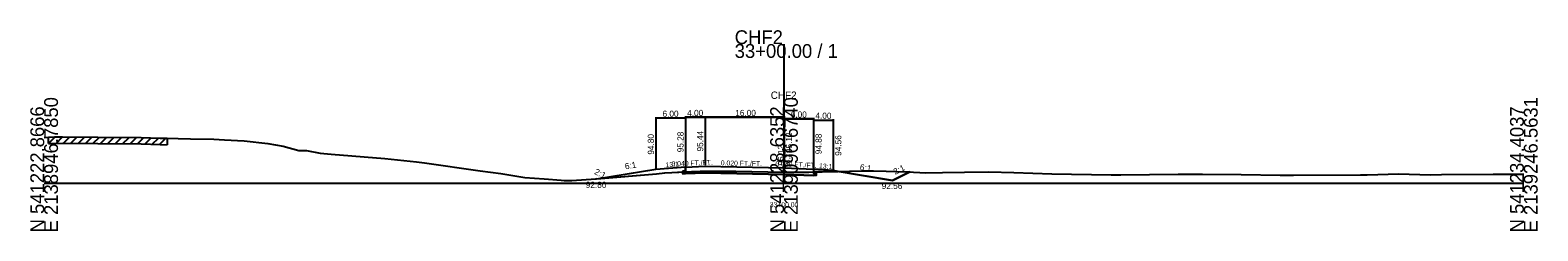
# Model space of a CAD drawing. Extents: x -12831 to 2303, y -10 to 39065.
# Drawn here: x 997.2 to 1302.8, y 5990.3 to 6031.1 of the extents above; entities that cross this region are included whole.
import ezdxf

# ---------------------------------------------------------------- set-up
doc = ezdxf.new("R2010")
doc.units = 0
for name, color, linetype in [('Level 5', 7, 'Continuous'), ('Level 53', 7, 'Continuous'), ('Level 54', 7, 'Continuous'), ('Level 55', 7, 'Continuous'), ('Level 7', 7, 'Continuous'), ('RD_GPK_XS_Cell', 7, 'Continuous'), ('RD_XS_EwShp', 7, 'Continuous'), ('RD_XS_ExGround', 7, 'Continuous'), ('RD_XS_ExPaveRet', 7, 'Continuous'), ('RD_XS_Pave', 7, 'Continuous'), ('RD_XS_TX_Baseline', 7, 'Continuous'), ('RD_XS_TX_Ditch', 7, 'Continuous'), ('RD_XS_TX_Elev_EX', 7, 'Continuous'), ('RD_XS_TX_Elev_PR', 7, 'Continuous'), ('RD_XS_TX_Station', 7, 'Continuous')]:
    doc.layers.add(name, color=color, linetype=linetype)

msp = doc.modelspace()

# ---------------------------------------------------------------- linework, layer by layer
at = {"layer": 'Level 5'}
for p, q in [((1130, 6002.45), (1129.5, 6002.43)), ((1129.5, 6002.43), (1129.5, 6001.93)), ((1129.5, 6001.93), (1130, 6001.95)), ((1130, 6003.28), (1130, 6002.45)), ((1134, 6002.11), (1130, 6001.95)), ((1134, 6002.11), (1130, 6001.95)), ((1130, 6001.95), (1134, 6002.11)), ((1150, 6001.79), (1134, 6002.11)), ((1150, 6001.79), (1134, 6002.11)), ((1134, 6002.11), (1150, 6001.79)), ((1134, 6002.11), (1150, 6001.79)), ((1156, 6001.55), (1150, 6001.79)), ((1150, 6001.79), (1156, 6001.55)), ((1150, 6001.79), (1156, 6001.55)), ((1156, 6002.88), (1156, 6002.05)), ((1156, 6002.05), (1156.5, 6002.03)), ((1156.5, 6001.53), (1156, 6001.55)), ((1156.5, 6002.03), (1156.5, 6001.53))]:
    msp.add_line(p, q, dxfattribs=at)
at = {"layer": 'Level 54'}
for p, q in [((1124, 6013.43), (1124, 6003)), ((1130, 6013.23), (1124, 6013.23)), ((1130, 6013.59), (1130, 6003.48)), ((1130, 6013.59), (1130, 6003.48)), ((1130, 6013.59), (1130, 6003.48)), ((1130, 6013.43), (1130, 6003.48)), ((1130, 6013.39), (1134, 6013.39)), ((1130, 6013.39), (1134, 6013.39)), ((1134, 6013.39), (1130, 6013.39)), ((1134, 6013.59), (1134, 6003.64)), ((1134, 6013.59), (1134, 6003.64)), ((1134, 6013.59), (1134, 6003.64)), ((1134, 6013.59), (1134, 6003.64)), ((1134, 6013.59), (1134, 6003.64)), ((1134, 6013.59), (1134, 6003.64)), ((1134, 6013.59), (1134, 6003.64)), ((1134, 6013.39), (1150, 6013.39)), ((1134, 6013.39), (1150, 6013.39)), ((1150, 6013.39), (1134, 6013.39)), ((1150, 6013.39), (1134, 6013.39)), ((1150, 6013.59), (1150, 6003.32)), ((1150, 6013.59), (1150, 6003.32)), ((1150, 6013.59), (1150, 6003.32)), ((1150, 6013.59), (1150, 6003.32)), ((1150, 6013.27), (1150, 6003.32)), ((1150, 6013.27), (1150, 6003.32)), ((1150, 6013.27), (1150, 6003.32)), ((1150, 6013.07), (1156, 6013.07)), ((1156, 6013.07), (1150, 6013.07)), ((1156, 6013.07), (1150, 6013.07)), ((1156, 6013.27), (1156, 6003.08)), ((1156, 6013.27), (1156, 6003.08)), ((1156, 6013.27), (1156, 6003.08)), ((1156, 6013.03), (1156, 6003.08)), ((1156, 6012.83), (1160, 6012.83)), ((1160, 6013.03), (1160, 6002.76))]:
    msp.add_line(p, q, dxfattribs=at)
at = {"layer": 'Level 7'}
for p, q in [((1112, 6000.8), (1111.88, 6000.86)), ((1124, 6002.8), (1112, 6000.8)), ((1130, 6003.28), (1124, 6002.8)), ((1156, 6002.88), (1160, 6002.56)), ((1160, 6002.56), (1172, 6000.56)), ((1172, 6000.56), (1175.48, 6002.3))]:
    msp.add_line(p, q, dxfattribs=at)
at = {"layer": 'RD_GPK_XS_Cell'}
for p, q in [((1150, 6000), (1150, 6028.25)), ((1000, 6000), (1150, 6000)), ((1150, 6000), (1300, 6000))]:
    msp.add_line(p, q, dxfattribs=at)
at = {"layer": 'RD_XS_EwShp'}
for points in [[(1112.84, 6000.94), (1112, 6000.8), (1111.88, 6000.86)], [(1112.84, 6000.94), (1124.13, 6001.88), (1125.81, 6002.1), (1127.26, 6002.18), (1129.5, 6002.29), (1129.5, 6002.43), (1130, 6002.45), (1130, 6003.28), (1124, 6002.8)], [(1129.5, 6002.29), (1132.97, 6002.46), (1140.22, 6002.46), (1146.75, 6002.3), (1150, 6002.27), (1153.19, 6002.25), (1155.01, 6002.26), (1156, 6002.28), (1156, 6002.05), (1156.5, 6002.03), (1156.5, 6001.53), (1156, 6001.55), (1150, 6001.79), (1134, 6002.11), (1130, 6001.95), (1129.5, 6001.93)], [(1156, 6002.28), (1160.97, 6002.4), (1160, 6002.56), (1156, 6002.88)], [(1168.13, 6002.54), (1170.73, 6002.44), (1175.07, 6002.33), (1175.48, 6002.3), (1172, 6000.56), (1160.97, 6002.4), (1165.98, 6002.51)]]:
    msp.add_lwpolyline(points, close=True, dxfattribs=at)
at = {"layer": 'RD_XS_ExGround'}
for p, q in [((1000, 6009.29), (1000.9, 6009.36)), ((1000.9, 6009.36), (1002.11, 6009.39)), ((1002.11, 6009.39), (1003.7, 6009.42)), ((1003.7, 6009.42), (1010.87, 6009.35)), ((1010.87, 6009.35), (1019.69, 6009.27)), ((1019.69, 6009.27), (1023.5, 6009.15)), ((1023.5, 6009.15), (1024.93, 6009.12)), ((1024.93, 6009.12), (1027.17, 6009.1)), ((1027.17, 6009.1), (1029.65, 6009.02)), ((1029.65, 6009.02), (1034.39, 6008.94)), ((1034.39, 6008.94), (1036.56, 6008.8)), ((1036.56, 6008.8), (1040.57, 6008.57)), ((1040.57, 6008.57), (1045.34, 6008.04)), ((1045.34, 6008.04), (1048.48, 6007.53)), ((1048.48, 6007.53), (1051.63, 6006.64)), ((1051.63, 6006.64), (1053.17, 6006.61)), ((1053.17, 6006.61), (1055.96, 6006.12)), ((1055.96, 6006.12), (1058.22, 6005.91)), ((1058.22, 6005.91), (1069.1, 6005.04)), ((1069.1, 6005.04), (1075.49, 6004.36)), ((1075.49, 6004.36), (1077.11, 6004.16)), ((1077.11, 6004.16), (1088.43, 6002.54)), ((1088.43, 6002.54), (1092.56, 6001.94)), ((1092.56, 6001.94), (1097.43, 6001.13)), ((1097.43, 6001.13), (1101.38, 6000.85)), ((1101.38, 6000.85), (1104.84, 6000.61)), ((1104.84, 6000.61), (1105.44, 6000.56)), ((1105.44, 6000.56), (1106.99, 6000.52)), ((1106.99, 6000.52), (1111.87, 6000.86)), ((1111.87, 6000.86), (1124.13, 6001.88)), ((1124.13, 6001.88), (1125.81, 6002.1)), ((1125.81, 6002.1), (1127.26, 6002.18)), ((1127.26, 6002.18), (1132.97, 6002.46)), ((1132.97, 6002.46), (1140.22, 6002.46)), ((1140.22, 6002.46), (1146.75, 6002.3)), ((1146.75, 6002.3), (1150, 6002.27)), ((1150, 6002.27), (1153.19, 6002.25)), ((1153.19, 6002.25), (1155.01, 6002.26)), ((1155.01, 6002.26), (1165.98, 6002.51)), ((1165.98, 6002.51), (1168.13, 6002.54)), ((1168.13, 6002.54), (1170.73, 6002.44)), ((1170.73, 6002.44), (1175.07, 6002.33)), ((1175.07, 6002.33), (1178.76, 6002.08)), ((1178.76, 6002.08), (1182.15, 6002.16)), ((1182.15, 6002.16), (1186.57, 6002.26)), ((1186.57, 6002.26), (1191.54, 6002.31)), ((1191.54, 6002.31), (1196.62, 6002.19)), ((1196.62, 6002.19), (1204.33, 6001.9)), ((1204.33, 6001.9), (1216.3, 6001.72)), ((1216.3, 6001.72), (1217.11, 6001.69)), ((1217.11, 6001.69), (1218.31, 6001.67)), ((1218.31, 6001.67), (1229.89, 6001.8)), ((1229.89, 6001.8), (1234.87, 6001.8)), ((1234.87, 6001.8), (1242.68, 6001.77)), ((1242.68, 6001.77), (1250.57, 6001.66)), ((1250.57, 6001.66), (1253.29, 6001.61)), ((1253.29, 6001.61), (1266.87, 6001.67)), ((1266.87, 6001.67), (1268.24, 6001.7)), ((1268.24, 6001.7), (1274.66, 6001.9)), ((1274.66, 6001.9), (1281.03, 6001.7)), ((1281.03, 6001.7), (1283.31, 6001.73)), ((1283.31, 6001.73), (1293.81, 6001.83)), ((1293.81, 6001.83), (1299.01, 6001.81)), ((1299.01, 6001.81), (1300, 6001.81))]:
    msp.add_line(p, q, dxfattribs=at)
at = {"layer": 'RD_XS_ExPaveRet'}
for p, q in [((1000.9, 6008.06), (1002.23, 6009.39)), ((1000.9, 6008.06), (1000.9, 6009.36)), ((1000.9, 6008.06), (1002.11, 6008.09)), ((1002.11, 6008.09), (1003.7, 6008.12)), ((1002.4, 6008.09), (1003.73, 6009.42)), ((1003.7, 6008.12), (1010.87, 6008.05)), ((1003.9, 6008.12), (1005.19, 6009.4)), ((1005.4, 6008.1), (1006.69, 6009.39)), ((1006.9, 6008.09), (1008.19, 6009.37)), ((1008.4, 6008.07), (1009.69, 6009.36)), ((1009.9, 6008.06), (1011.19, 6009.34)), ((1010.87, 6008.05), (1019.69, 6007.97)), ((1011.41, 6008.04), (1012.69, 6009.33)), ((1012.91, 6008.03), (1014.2, 6009.32)), ((1014.41, 6008.02), (1015.7, 6009.31)), ((1015.91, 6008), (1017.2, 6009.29)), ((1017.41, 6007.99), (1018.7, 6009.28)), ((1018.91, 6007.98), (1020.19, 6009.26)), ((1019.69, 6007.97), (1023.5, 6007.85)), ((1020.41, 6007.95), (1021.67, 6009.21)), ((1021.91, 6007.9), (1023.17, 6009.16)), ((1023.41, 6007.85), (1024.68, 6009.12)), ((1023.5, 6007.85), (1024.93, 6007.82)), ((1024.93, 6009.12), (1024.93, 6007.82))]:
    msp.add_line(p, q, dxfattribs=at)
at = {"layer": 'RD_XS_Pave'}
for p, q in [((1130, 6003.28), (1134, 6003.44)), ((1134, 6003.44), (1150, 6003.12)), ((1150, 6003.12), (1156, 6002.88))]:
    msp.add_line(p, q, dxfattribs=at)

# ---------------------------------------------------------------- texts
at = {"layer": 'Level 53'}
for s, rotation, p in [('94.80', 90, (1123.63, 6005.8)), ('95.28', 90, (1129.63, 6006.28)), ('95.44', 90, (1133.62, 6006.44)), ('95.44', 90, (1133.62, 6006.44)), ('95.12', 90, (1151.63, 6006.12)), ('95.12', 90, (1151.63, 6006.12)), ('94.88', 90, (1157.63, 6005.88)), ('94.56', 90, (1161.63, 6005.56)), ('6:1', 9.4623, (1117.84, 6002.79)), ('6:1', 350.5377, (1165.3, 6002.69))]:
    msp.add_text(s, height=1.25, rotation=rotation, dxfattribs=at).set_placement(p)
msp.add_text('92.56', height=1.25, dxfattribs=at).set_placement((1169.81, 5998.81))
at = {"layer": 'Level 54'}
for s, p in [('6.00', (1125.37, 6013.48)), ('4.00', (1130.37, 6013.64)), ('4.00', (1130.37, 6013.64)), ('4.00', (1130.37, 6013.64)), ('16.00', (1140.12, 6013.64)), ('16.00', (1140.12, 6013.64)), ('16.00', (1140.12, 6013.64)), ('16.00', (1140.12, 6013.64)), ('6.00', (1151.37, 6013.32)), ('6.00', (1151.37, 6013.32)), ('6.00', (1151.37, 6013.32)), ('4.00', (1156.37, 6013.08))]:
    msp.add_text(s, height=1.25, dxfattribs=at).set_placement(p)
at = {"layer": 'Level 55'}
for s, height, rotation, p in [('13:1', 1, 4.5739, (1126.03, 6003.21)), ('0.040 FT./FT.', 1, 2.2906, (1127.22, 6003.42)), ('0.040 FT./FT.', 1, 2.2906, (1127.22, 6003.42)), ('0.040 FT./FT.', 1, 2.2906, (1127.22, 6003.42)), ('0.020 FT./FT.', 1, 358.8542, (1137.18, 6003.63)), ('0.020 FT./FT.', 1, 358.8542, (1137.18, 6003.63)), ('0.020 FT./FT.', 1, 358.8542, (1137.18, 6003.63)), ('0.020 FT./FT.', 1, 358.8542, (1137.18, 6003.63)), ('0.040 FT./FT.', 1, 357.7094, (1148.24, 6003.44)), ('0.040 FT./FT.', 1, 357.7094, (1148.24, 6003.44)), ('0.040 FT./FT.', 1, 357.7094, (1148.24, 6003.44)), ('13:1', 1, 355.4261, (1157.07, 6003.05)), ('2:1', 1.25, 26.5651, (1172.56, 6001.68)), ('2:1', 1.25, 333.4349, (1111.43, 6001.92))]:
    msp.add_text(s, height=height, rotation=rotation, dxfattribs=at).set_placement(p)
at = {"layer": 'RD_GPK_XS_Cell'}
for s, p in [('33+00.00 / 1', (1140, 6025.45)), ('CHF2', (1140, 6028.25))]:
    msp.add_text(s, height=2.8, dxfattribs=at).set_placement(p)
for s, p in [('E 2138946.7850', (1002.8, 5990)), ('E 2139096.6740', (1152.8, 5990)), ('E 2139246.5631', (1302.8, 5990)), ('N 541222.8666', (1000, 5990)), ('N 541228.6352', (1150, 5990)), ('N 541234.4037', (1300, 5990))]:
    msp.add_text(s, height=2.8, rotation=90, dxfattribs=at).set_placement(p)
at = {"layer": 'RD_XS_TX_Baseline'}
msp.add_text('CHF2', height=1.5, dxfattribs=at).set_placement((1147.31, 6017.12))
at = {"layer": 'RD_XS_TX_Ditch'}
msp.add_text('92.80', height=1.25, dxfattribs=at).set_placement((1109.81, 5999.05))
at = {"layer": 'RD_XS_TX_Elev_EX'}
msp.add_text('94.27', height=1, rotation=90, dxfattribs=at).set_placement((1151.25, 6003.27))
at = {"layer": 'RD_XS_TX_Elev_PR'}
msp.add_text(' 95.12', height=1.25, rotation=90, dxfattribs=at).set_placement((1150, 6003.12))
at = {"layer": 'RD_XS_TX_Station'}
msp.add_text('33+00.00', height=1, dxfattribs=at).set_placement((1147.11, 5995.12))

doc.saveas('drawing.dxf')
